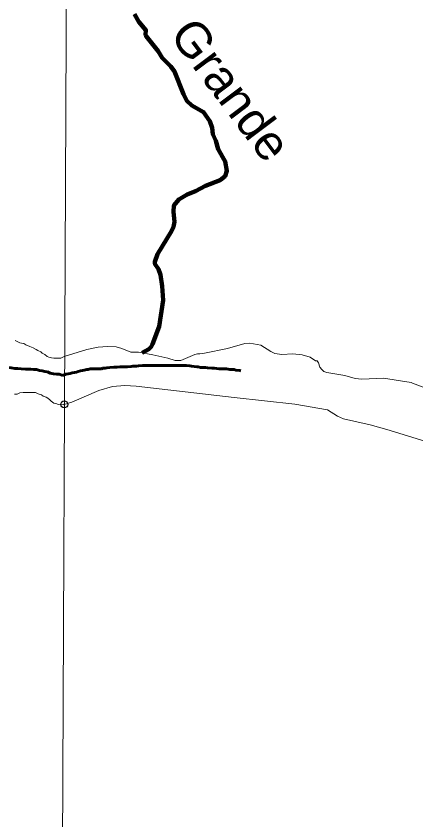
# Model space of a CAD drawing. Extents: x -1643653 to 4543381, y 1624270 to 13878484.
# Drawn here: x 663836 to 669599, y 8915829 to 8927410 of the extents above; entities that cross this region are included whole.
import ezdxf

# ---------------------------------------------------------------- set-up
doc = ezdxf.new("R2010")
doc.units = 0
doc.header["$LTSCALE"] = 200
doc.header["$PDMODE"] = 32
doc.header["$PDSIZE"] = 100
doc.linetypes.add('LONG_DASH_SHORT_DASH', pattern=[9.9, 6, -1.2, 1.5, -1.2])
for name, color, linetype, lineweight in [('1', 7, 'Continuous', 13), ('24', 7, 'Continuous', 25), ('25', 7, 'Continuous', 13), ('53', 7, 'Continuous', 106), ('57', 7, 'Continuous', 13), ('60', 7, 'Continuous', 13), ('7', 7, 'LONG_DASH_SHORT_DASH', 60)]:
    doc.layers.add(name, color=color, linetype=linetype, lineweight=lineweight)
doc.layers.add('49', color=7, linetype='Continuous')

msp = doc.modelspace()

# ---------------------------------------------------------------- linework, layer by layer
at = {"layer": '1'}
msp.add_lwpolyline([(664968.2, 9023436.8), (664657.1, 8949509), (664397.1, 8890880.2)], dxfattribs=at)
at = {"layer": '24'}
msp.add_line((666737.2, 8925710.7), (666737.9, 8925710.1), dxfattribs=at)
for points in [[(665884.6, 8926902.1), (665710.7, 8927118.6), (665703.5, 8927141.6), (665707.3, 8927207.3), (665604.7, 8927327.2), (665543.5, 8927435.1)], [(665654.1, 8922558.1), (665747.4, 8922613.4), (665782.6, 8922644.9), (665804.2, 8922685), (665898.2, 8922937), (665956.6, 8923316.8), (665944.3, 8923521), (665915.9, 8923680.3), (665887.1, 8923762.6), (665837.8, 8923840.4), (665834.9, 8923868.6), (665876, 8923981.1), (666075.9, 8924311.2), (666104.4, 8924374.8), (666118.2, 8924447.8), (666103.2, 8924589.1), (666111.8, 8924680), (666180.2, 8924767.7), (666303.3, 8924840.7), (666423.2, 8924888.8), (666567, 8924965.4), (666778.1, 8925046.5), (666849.4, 8925104.6), (666875.5, 8925182.5), (666852.3, 8925317.2), (666747.4, 8925494.9), (666714.9, 8925611.2), (666674, 8925709.5), (666660.9, 8925800.8), (666626.8, 8925897.6), (666539.3, 8926027.5), (666367.3, 8926123.4), (666298.2, 8926188.4), (666251.5, 8926283.4), (666120.6, 8926610.3), (666067.4, 8926681.3), (665942.6, 8926807.9), (665884.6, 8926902.1)], [(665804.2, 8922685), (665782.6, 8922644.9), (665747.4, 8922613.4), (665654.1, 8922558.1)]]:
    msp.add_lwpolyline(points, dxfattribs=at)
msp.add_point((664531.1, 8921815.4), dxfattribs=at)
at = {"layer": '25'}
for points in [[(663825.6, 8922735.4), (663850.5, 8922720.2), (663890.4, 8922704.9), (663912.8, 8922697.3), (663950.3, 8922692), (663977.7, 8922674.3), (664032.5, 8922648.9), (664084.9, 8922631), (664127.3, 8922608.2), (664152.1, 8922590.5), (664192, 8922572.8), (664211.9, 8922552.6), (664249.2, 8922534.8), (664286.5, 8922504.5), (664309, 8922496.9), (664348.9, 8922486.6), (664381.4, 8922481.4), (664416.4, 8922481.1), (664436.4, 8922481), (664461.5, 8922483.3), (664481.5, 8922483.2), (664531.1, 8922504.7), (664855.7, 8922606.1), (665018.2, 8922640.1), (665151.9, 8922649.8), (665276.6, 8922642.6), (665359.5, 8922619.8)], [(665807.2, 8922530.5), (665805.3, 8922529), (666021.2, 8922480.8), (666128.1, 8922448.4), (666212.6, 8922450.2), (666414.1, 8922533.6), (666451.7, 8922544.9), (666486.4, 8922546.2), (666551.6, 8922551.4), (666883.2, 8922619.3), (667134.9, 8922692.2), (667207.8, 8922696.8), (667366, 8922668.8), (667507, 8922579.6), (667567.9, 8922550.4), (667666.3, 8922536.7), (667827.1, 8922544.8), (667960.2, 8922528.3), (668076.2, 8922494.1), (668149.9, 8922444.5), (668175.3, 8922440.9), (668193.4, 8922414.2), (668215.8, 8922353.1), (668240.8, 8922316.8), (668270.3, 8922290.6), (668317.3, 8922273.5), (668576.3, 8922231.4), (668724.7, 8922190.8), (668817.5, 8922180.4), (669130.5, 8922192.7), (669530, 8922132.2)], [(665359.5, 8922619.8), (665492.3, 8922568.3), (665600, 8922565.9), (665805.3, 8922529)], [(669530, 8922132.2), (669551.5, 8922120.6), (669703.5, 8922065.4)], [(664531.1, 8921815.4), (664483.8, 8921807.2), (664446.4, 8921815), (664411.5, 8921827.8), (664379, 8921835.5), (664344.2, 8921863.2), (664321.8, 8921880.9), (664292, 8921903.7), (664269.6, 8921918.8), (664224.7, 8921936.6), (664202.3, 8921954.3), (664152.4, 8921969.7), (664117.5, 8921984.9), (664070, 8921987.7), (664027.5, 8921988), (663982.5, 8921988.3), (663937.5, 8921988.6), (663892.4, 8921983.9), (663849.7, 8921964.2), (663814.7, 8921964.4)], [(670613, 8921062.4), (670594.6, 8921075.1), (670505.7, 8921092.1), (670378.9, 8921097.7), (670172.5, 8921136.1), (669790.2, 8921268), (669181.6, 8921455.5), (668940.4, 8921522.2), (668553.3, 8921609.1), (668470.6, 8921646), (668322.8, 8921739.3), (667855.1, 8921816.8), (666980.9, 8921915.9), (665565.9, 8922078.1), (665402.5, 8922087.8), (665227.8, 8922071.5), (665027.5, 8922015.6), (664640.9, 8921845.5), (664531.1, 8921815.4)]]:
    msp.add_lwpolyline(points, dxfattribs=at)
msp.add_point((664531.1, 8921815.4), dxfattribs=at)
at = {"layer": '53'}
for points in [[(665884.6, 8926902.1), (665710.7, 8927118.6), (665703.5, 8927141.6), (665707.3, 8927207.3), (665604.7, 8927327.2), (665543.5, 8927435.1)], [(665654.1, 8922558.1), (665747.4, 8922613.4), (665782.6, 8922644.9), (665804.2, 8922685), (665898.2, 8922937), (665956.6, 8923316.8), (665944.3, 8923521), (665915.9, 8923680.3), (665887.1, 8923762.6), (665837.8, 8923840.4), (665834.9, 8923868.6), (665876, 8923981.1), (666075.9, 8924311.2), (666104.4, 8924374.8), (666118.2, 8924447.8), (666103.2, 8924589.1), (666111.8, 8924680), (666180.2, 8924767.7), (666303.3, 8924840.7), (666423.2, 8924888.8), (666567, 8924965.4), (666778.1, 8925046.5), (666849.4, 8925104.6), (666875.5, 8925182.5), (666852.3, 8925317.2), (666747.4, 8925494.9), (666714.9, 8925611.2), (666674, 8925709.5), (666660.9, 8925800.8), (666626.8, 8925897.6), (666539.3, 8926027.5), (666367.3, 8926123.4), (666298.2, 8926188.4), (666251.5, 8926283.4), (666120.6, 8926610.3), (666067.4, 8926681.3), (665942.6, 8926807.9), (665884.6, 8926902.1)]]:
    msp.add_lwpolyline(points, dxfattribs=at)
at = {"layer": '57'}
for points in [[(664531.1, 8922504.7), (664481.5, 8922483.2), (664461.5, 8922483.3), (664436.4, 8922481), (664416.4, 8922481.1), (664381.4, 8922481.4), (664348.9, 8922486.6), (664309, 8922496.9), (664286.5, 8922504.5), (664249.2, 8922534.8), (664211.9, 8922552.6), (664192, 8922572.8), (664152.1, 8922590.5), (664127.3, 8922608.2), (664084.9, 8922631), (664032.5, 8922648.9), (663977.7, 8922674.3), (663950.3, 8922692), (663912.8, 8922697.3), (663890.4, 8922704.9), (663850.5, 8922720.2), (663825.6, 8922735.4)], [(663825.6, 8922735.4), (663850.5, 8922720.2), (663890.4, 8922704.9), (663912.8, 8922697.3), (663950.3, 8922692), (663977.7, 8922674.3), (664032.5, 8922648.9), (664084.9, 8922631), (664127.3, 8922608.2), (664152.1, 8922590.5), (664192, 8922572.8), (664211.9, 8922552.6), (664249.2, 8922534.8), (664286.5, 8922504.5), (664309, 8922496.9), (664348.9, 8922486.6), (664381.4, 8922481.4), (664416.4, 8922481.1), (664436.4, 8922481), (664461.5, 8922483.3), (664481.5, 8922483.2), (664531.1, 8922504.7), (664855.7, 8922606.1), (665018.2, 8922640.1), (665151.9, 8922649.8), (665276.6, 8922642.6), (665359.5, 8922619.8)], [(669530, 8922132.2), (669130.5, 8922192.7), (668817.5, 8922180.4), (668724.7, 8922190.8), (668576.3, 8922231.4), (668317.3, 8922273.5), (668270.3, 8922290.6), (668240.8, 8922316.8), (668215.8, 8922353.1), (668193.4, 8922414.2), (668175.3, 8922440.9), (668149.9, 8922444.5), (668076.2, 8922494.1), (667960.2, 8922528.3), (667827.1, 8922544.8), (667666.3, 8922536.7), (667567.9, 8922550.4), (667507, 8922579.6), (667366, 8922668.8), (667207.8, 8922696.8), (667134.9, 8922692.2), (666883.2, 8922619.3), (666551.6, 8922551.4), (666486.4, 8922546.2), (666451.7, 8922544.9), (666414.1, 8922533.6), (666212.6, 8922450.2), (666128.1, 8922448.4), (666021.2, 8922480.8), (665805.3, 8922529), (665807.2, 8922530.5), (665805.3, 8922529), (665600, 8922565.9), (665492.3, 8922568.3), (665359.5, 8922619.8), (665276.6, 8922642.6), (665151.9, 8922649.8), (665018.2, 8922640.1), (664855.7, 8922606.1), (664531.1, 8922504.7)], [(665807.2, 8922530.5), (665805.3, 8922529), (666021.2, 8922480.8), (666128.1, 8922448.4), (666212.6, 8922450.2), (666414.1, 8922533.6), (666451.7, 8922544.9), (666486.4, 8922546.2), (666551.6, 8922551.4), (666883.2, 8922619.3), (667134.9, 8922692.2), (667207.8, 8922696.8), (667366, 8922668.8), (667507, 8922579.6), (667567.9, 8922550.4), (667666.3, 8922536.7), (667827.1, 8922544.8), (667960.2, 8922528.3), (668076.2, 8922494.1), (668149.9, 8922444.5), (668175.3, 8922440.9), (668193.4, 8922414.2), (668215.8, 8922353.1), (668240.8, 8922316.8), (668270.3, 8922290.6), (668317.3, 8922273.5), (668576.3, 8922231.4), (668724.7, 8922190.8), (668817.5, 8922180.4), (669130.5, 8922192.7), (669530, 8922132.2)], [(665359.5, 8922619.8), (665492.3, 8922568.3), (665600, 8922565.9), (665805.3, 8922529)], [(669703.5, 8922065.4), (669551.5, 8922120.6), (669530, 8922132.2)], [(669530, 8922132.2), (669551.5, 8922120.6), (669703.5, 8922065.4)]]:
    msp.add_lwpolyline(points, dxfattribs=at)
at = {"layer": '60', "lineweight": 25}
msp.add_spline([(814781, 9009175.5), (814787.2, 9009173.4), (814796.9, 9009173.4), (814799.4, 9009172.4), (814805.1, 9009174.5), (814805.6, 9009176.5), (814811.7, 9009179.5), (814811.7, 9009179.5), (814801.5, 9009181), (814790.7, 9009181.5), (814784.1, 9009183.1), (814777.4, 9009185.1), (814778.4, 9009175.5)], degree=3, dxfattribs=at)
at = {"layer": '7'}
for points in [[(664555.3, 8922251.1), (664510.5, 8922233.7), (664455.6, 8922249), (664420.6, 8922251.7), (664375.7, 8922254.4), (664325.7, 8922267.2), (664288.3, 8922282.4), (664250.9, 8922287.6), (664213.5, 8922300.3), (664176, 8922305.6), (664128.6, 8922318.3), (664086.1, 8922318.5), (664048.6, 8922321.2), (663973.6, 8922324.1), (663908.6, 8922327), (663861.2, 8922332.2), (663816.2, 8922335), (663763.7, 8922340.3), (663706.2, 8922345.6)], [(666977.6, 8922317.6), (666919.1, 8922320.2), (666870.8, 8922327.8), (666842.8, 8922327.8), (666799.5, 8922330.4), (666761.3, 8922330.4), (666692.6, 8922335.5), (666657, 8922338), (666595.9, 8922340.6), (666565.4, 8922345.7), (666519.6, 8922348.3), (666496.7, 8922348.3), (666461.1, 8922355.9), (666440.7, 8922358.5), (666405.1, 8922361), (666366.9, 8922366.2), (666338.9, 8922371.3), (666290.6, 8922376.4), (666227, 8922376.4), (666168.5, 8922376.4), (666140.5, 8922376.4), (666092.1, 8922376.4), (666061.6, 8922376.4), (665980.2, 8922376.4), (665944.5, 8922376.4), (665886, 8922376.4), (665855.5, 8922376.4), (665799.5, 8922376.4), (665769, 8922376.4), (665697.7, 8922376.4), (665659.6, 8922376.4), (665601, 8922371.2), (665570.5, 8922368.7), (665519.6, 8922366.1), (665494.2, 8922361), (665443.3, 8922355.9), (665400, 8922355.9), (665377.1, 8922355.9), (665333.9, 8922355.9), (665293.2, 8922350.8), (665244.8, 8922350.8), (665188.8, 8922348.2), (665145.6, 8922340.6), (665122.7, 8922338), (665087.1, 8922335.5), (665066.7, 8922330.3), (665018.4, 8922327.8), (664987.8, 8922327.8), (664962.4, 8922327.8), (664934.4, 8922327.8), (664903.9, 8922327.8), (664875.9, 8922320.1), (664855.5, 8922320.1), (664819.9, 8922309.9), (664791.9, 8922304.8), (664763.9, 8922297.1), (664733.4, 8922289.4), (664708, 8922281.8), (664677.4, 8922276.7), (664646.9, 8922269), (664616.4, 8922261.3), (664585.8, 8922256.2), (664555.3, 8922251.1), (664555.3, 8922251.1), (664555.3, 8922251.1)], [(667073.5, 8922301.6), (667059.1, 8922304.8), (667005.6, 8922309.9), (666977.6, 8922317.6)]]:
    msp.add_lwpolyline(points, dxfattribs=at)

# ---------------------------------------------------------------- texts
at = {"layer": '49', "width": 1.05}
msp.add_text('Grande', height=500, rotation=306.886, dxfattribs=at).set_placement((666032.2, 8927138.1))

doc.saveas('drawing.dxf')
